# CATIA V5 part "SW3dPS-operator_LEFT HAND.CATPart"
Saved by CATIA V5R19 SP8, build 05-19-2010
Part number: SW3dPS-operator_LEFT HAND
Revision: ANY
Definition: SW3dPS-operator_LEFT HAND
Source: Unknown
Bounding box of the stored display mesh (mm): x -69.85 to 185.216, y -77.34 to 31.75, z 313.766 to 411.556
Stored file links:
  G:\EU_thinkMotion\CFAO_2010\MMS_groupe1\MMS_groupe1\OK\rragonneau\rragonneau\SW3dPS-operator_LEFT HAND.CATPart
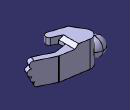
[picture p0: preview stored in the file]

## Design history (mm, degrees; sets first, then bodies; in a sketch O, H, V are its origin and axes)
Body1 "NONE" (main body)
  Solid1 "Manifold Solid #11343": solid without history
